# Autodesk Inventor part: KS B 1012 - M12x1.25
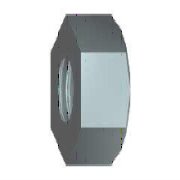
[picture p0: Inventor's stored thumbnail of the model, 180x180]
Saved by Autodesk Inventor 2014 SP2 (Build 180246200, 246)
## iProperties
IsCustomPart: 0
Created: 2009-02
Part Number: KS B 1012 - M12x1.25
Material: 강, 연강
Description: 6각 너트
Document SubType Name: Modeling
Standard: KS B 1012
Designer: KYOUNG IL JANG
Standards Organization: KS
Language: ko-KR
Size Designation: M12x1.25
Categories: <MemberInstance><Categories><Category DisplayName="조임쇠" InternalName="e4da775c-781d-43d5-af7c-5136215cf5a6" Mnemonic="FSTN"><Category DisplayName="너트" InternalN
Density: 1 g/cm^3
Appearance: 강철
Author: KYOUNG IL JANG
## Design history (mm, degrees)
sketch "스케치1"
  geometry: L1 (10.97, 0)-(5.485, -9.5); L2 (5.485, -9.5)-(-5.485, -9.5); L3 (-5.485, -9.5)-(-10.97, 0); L4 (-10.97, 0)-(-5.485, 9.5); L5 (-5.485, 9.5)-(5.485, 9.5); L6 (5.485, 9.5)-(10.97, 0); 2 further points
  constraints: 12 end point, 1 coincident, 1 horizontal, 11 other
  dimensions: "d0" = 21.93931 distance of L1.start L3.end (= 1.1547 x SW)
extrude "본체" new body sketch "스케치1" distance "d1" = 10 (= KOH); taper "d2" = 0 deg
sketch "스케치2"
  geometry: 1 further point
hole "스레드" sketch "스케치2" diameter "d6" = 10.647; stored, may be unused: countersink angle "d10" = 82 deg, drill point angle "d12" = 118 deg; dims "d7" = 12.7, "d8" = 9.525, "d9" = 6.35, "d11" = 19.05
sketch "스케치3"
  geometry: L1 (0, 10.97)-(10, 10.97) reference; L2 (10, 5.485)-(10, 10.97) reference; L3 (-2, 0)-(12, 0) reference; L4 (9.151, 10.97)-(10, 9.5)
  constraints: 2 end point, 2 point on line
  dimensions: "d3" = 19 diameter of L4.end L3 (= SW01); "d4" = 30 deg angle of L2 L4 (= ANG2)
revolve "모따기3" sketch "스케치3" stored, may be unused: angle "d5" = 90 deg
workaxis "Work Axis1"
workplane "Work Plane1"
body "Solid1"
chamfer "모따기1" distance "d13" = 0.67658 (= -0.5 x GD1 + 0.5 x NND); stored, may be unused: angle "d14" = 30 deg, second distance "d21" = 0.67658 (= -0.5 x GD1 + 0.5 x NND)
chamfer "모따기2" distance "d15" = 0.67658 (= -0.5 x GD1 + 0.5 x NND); stored, may be unused: angle "d16" = 30 deg, second distance "d22" = 0.67658 (= -0.5 x GD1 + 0.5 x NND)
other parameters: "ANG2" = 30 deg [user parameter; used in 1 equation term], "NND" = 12 [user parameter; used in 4 equation terms], "KOH" = 10 [user parameter; used in 1 equation term], "SW" = 19 [user parameter; used in 3 equation terms], "SW01" = 19 (= SW) [user parameter; used in 1 equation term], "GD1" = 10.64684 (computed from THREADDIA, PTC, TOA) [user parameter; used in 4 equation terms], "d19" = 0, "d20" = 0, "d24" = 0, "d25" = 0, "GUL" = 0.67658 (= 0.541266 x PTC) [user parameter], "TPU" = 8 (computed from PTC) [user parameter], "TOA" = 30 deg [user parameter; used in 1 equation term], "PTC" = 1.25 [user parameter; used in 4 equation terms], "E0" = 21.945 (= 1.155 x SW) [user parameter], "THREADDIA" = 12 [user parameter; used in 1 equation term], "GAL" = 0.67658 (= 0.541266 x PTC) [user parameter]
